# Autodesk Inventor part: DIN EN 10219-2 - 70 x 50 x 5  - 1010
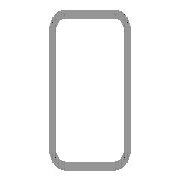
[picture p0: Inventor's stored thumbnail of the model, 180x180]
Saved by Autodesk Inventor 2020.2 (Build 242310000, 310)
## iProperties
Created: 2019-01
Part Number: DIN EN 10219-2 - 70 x 50 x 5  - 1010
Material: Stahl, weich
Description: Kaltgeformte, geschweißte Baustahl-Hohlprofile aus unlegiertem Feinkorn-Baustahl
Document SubType Name: Modeling
Standard: DIN EN 10219-2
Designer: lutzd
Standard Revision: 2006-07
Standards Organization: DIN
Language: de-DE
Size Designation: 70 x 50 x 5
Categories: <MemberInstance><Categories><Category DisplayName="Profile" InternalName="089c4875-fa83-4c05-b084-43b9cc11f5ed" Mnemonic="GRDR"><CategoryParameter DisplayName="
Stock Number: 70 x 50 x 5
Mass: 8208.18 g
Surface Area: 4205.32 cm^2
Volume: 1045.63 cm^3
Density: 7.85 g/cm^3
Appearance: Semi-Polished(8)
IsCustomPart: 1
G_W: 50,000 mm
G_H: 70,000 mm
G_L: 1010,000 mm
+9469D395-AB8B-429F-9B45-4FB77757C930+SCHNITTDETAIL1: Schnittwinkel 90,00 grd
+1AB871F0-0E74-4D49-AA31-872F57F6F057+SCHNITTDETAIL2: Schnittwinkel 90,00 grd
DocNumber: ADSK-014408
Folder: .
Mass: 8,208 kg
VLT_Material: Stahl, weich
Dimensions: 50x70x1010 mm
_CCFamilyMember: 17
_CCFamilyDisplayName: DIN EN 10219-2 (Rechteckiges Hohlprofil - Kaltgeformt) - Kaltgeformte, geschweißte Baustahl-Hohlprofile aus unlegiertem Feinkorn-Baustahl
_FrameMemberDoc: Frame Member File
_Version: 15.0.0
_GetPNFromCC: 1
Title: Profil-Bauteil
Author: lutzd
Revision Number: -
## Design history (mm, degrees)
node "Startebene"
node "Endebene"
sketch "Skizze"
  geometry: L1 (-25, -25)-(-25, 25); L2 (-15, 35)-(15, 35); L3 (25, 25)-(25, -25); L4 (15, -35)-(-15, -35); L5 (-15, 30)-(15, 30); L6 (20, 25)-(20, -25); L7 (15, -30)-(-15, -30); L8 (-20, -25)-(-20, 25); L9 (0, 51.899)-(0, -51.899) reference; L10 (-37.899, 0)-(37.899, 0) reference; A1 r 10 centre (-15, -25) between (-25, -25) and (-15, -35); A2 r 10 centre (-15, 25) between (-15, 35) and (-25, 25); A3 r 10 centre (15, 25) between (25, 25) and (15, 35); A4 r 10 centre (15, -25) between (15, -35) and (25, -25); A5 r 5 centre (-15, 25) between (-15, 30) and (-20, 25); A6 r 5 centre (15, 25) between (20, 25) and (15, 30); A7 r 5 centre (15, -25) between (15, -30) and (20, -25); A8 r 5 centre (-15, -25) between (-20, -25) and (-15, -30)
  constraints: 16 end point, 16 point on circle, 8 centre point, 8 tangent, 4 parallel, 3 equal radius, 2 perpendicular, 7 other
  dimensions: "d7" = 10 radius of A1 (= G_IR); "d10" = 70 distance between parallel lines of L2 L4 (= G_H); "d11" = 50 distance between parallel lines of L1 L3 (= G_W); "d12" = 5 distance between parallel lines of L3 L6 (= G_T); "d15" = 35 distance between parallel lines of L2 L10 (= 0.5 x d10); "d16" = 25 distance between parallel lines of L9 L3 (= 0.5 x d11)
extrude "Körper" new body sketch "Skizze" stored distance "d3" = 1010 (= G_L); taper "d4" = 0 deg
node "Driven Length"
  sketch "Sketch3"
    geometry: L1 (0, 0)-(10, 0) reference
    constraints: 2 end point, 1 horizontal
  workplane "Work Plane3"
  sketch "Sketch4"
    geometry: L1 (-2, 50)-(12, 50) reference; L2 (-2, 1060)-(12, 1060) reference
    dimensions: "d18" = 1010 distance between parallel lines of L1 L2 (derived)
workplane "Arbeitsebene4"
feature "Trennen1"
workplane "Arbeitsebene5"
feature "Trennen2"
sketch "Skizze5"
  geometry: L1 (0, -50)-(0, 0) reference; L2 (0, -25)-(439.5, -25); 3 further points
  constraints: 2 end point, 1 coincident, 1 horizontal, 1 midpoint, 1 point on line
  dimensions: "d19" = 80 distance of point (359.5, -25) point (439.5, -25); "d20" = 439.5 distance of L2.start L2.end
hole "Bohrung1" sketch "Skizze5" at (439.5, -25), (359.5, -25) diameter "d21" = 6.647; stored, may be unused: countersink angle "d25" = 90 deg, drill point angle "d27" = 118 deg; dims "d22" = 16, "d23" = 4, "d24" = 2, "d26" = 8
body "Solid1"
other parameters: "G_W" = 50 [user parameter; used in 1 equation term], "G_H" = 70 [user parameter; used in 1 equation term], "G_T" = 5 [user parameter; used in 1 equation term], "G_IR" = 10 [user parameter; used in 1 equation term], "G_L" = 1010 (= d18) [user parameter; used in 1 equation term], "G_OFFSET_END" = -25 [user parameter; used in 1 equation term], "B_L" = 1085 [user parameter; used in 1 equation term], "d17" = 90 deg
